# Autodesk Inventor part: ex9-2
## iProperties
Author: Administrator
Created: 2001-09
Part Number: ex9-2
Document SubType Name: Sheet Metal
Designer: Administrator
Control State: 0
Master: False
Checked Out: False
PropertySet Name: Design Tracking Control
Length Units: 11272
Angle Units: 11279
Time Units: 11290
Mass Units: 11286
Shininess: 3
Angle Display Precision: 2
Document Length Units: 11272
Document Angle Units: 11286
Document Time Units: 11279
Document Mass Units: 11290
Document Length Units Precision: 3
Document Angle Units Precision: 2
Compacted: False
PropertySet Name: _Private Model Information
Density: 0.0
Volumn: 0.0
Area: 0.0
PropertySet Name: Model Information
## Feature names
1. Plate1
2. Bend1
3. Cut1
